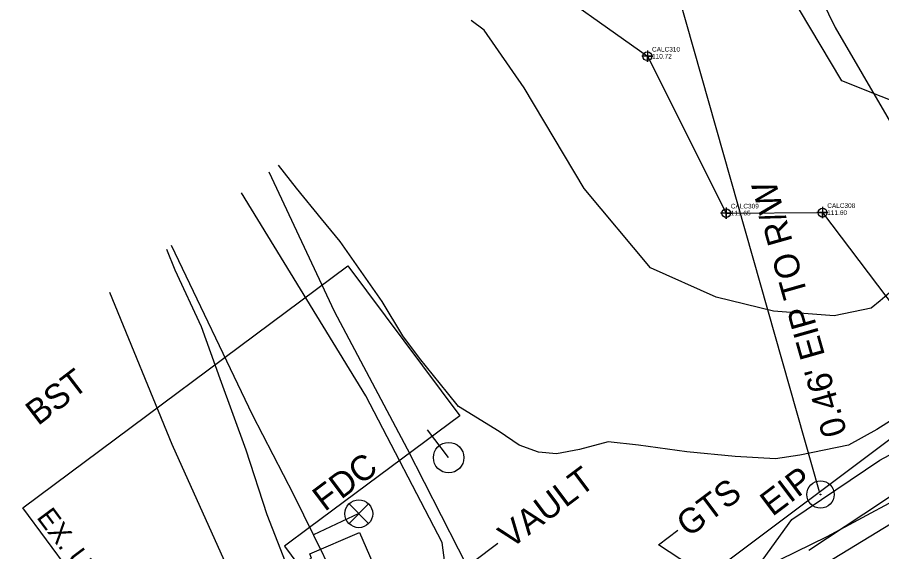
# Model space of a CAD drawing. Extents: x 2186615 to 2188822, y 629899 to 631820.
# Drawn here: x 2187114.7 to 2187253.2, y 630486.1 to 630571.8 of the extents above; entities that cross this region are included whole.
import ezdxf

# ---------------------------------------------------------------- set-up
doc = ezdxf.new("R2010")
doc.units = 0
for name, color, linetype in [('Exist Environmental Wetland Boundary', 7, 'Continuous'), ('Exist Environmental Wetland Boundary Cogo Elevation', 7, 'Continuous'), ('Exist Environmental Wetland Boundary Cogo Number', 7, 'Continuous'), ('Exist Environmental Wetland Boundary Cogo Point CELL', 7, 'Continuous'), ('Exist Guardrail', 7, 'Continuous'), ('Exist Hydro Stream or Body of Water', 7, 'Continuous'), ('Exist Other Culture Area Outline', 7, 'Continuous'), ('Exist Other Culture Area Outline Leader', 7, 'Continuous'), ('Exist Other Culture Area Outline Text', 7, 'Continuous'), ('Exist Other Culture Located Object Leader', 7, 'Continuous'), ('Exist Other Culture Located Object Text', 7, 'Continuous'), ('Exist Property Iron Pin CELL', 7, 'Continuous'), ('Exist Property Iron Pin Text', 7, 'Continuous'), ('Exist Property Line', 7, 'Continuous'), ('Exist Property Line Text', 7, 'Continuous'), ('Exist Right of Way Easement Line', 7, 'Continuous'), ('Exist Right of Way Easement Line Text', 7, 'Continuous'), ('Exist Right of Way Line', 7, 'Continuous'), ('Exist Roads EOP Other', 7, 'Continuous'), ('Exist Roads EOP Text', 7, 'Continuous'), ('Exist Utilities Gas UG Line SUE LOS B', 7, 'Continuous'), ('Exist Utilities Power Pole CELL', 7, 'Continuous'), ('Exist Utilities Telephone UG FO SUE LOS B', 7, 'Continuous'), ('Exist Utilities TV UG Cable SUE LOS B', 7, 'Continuous'), ('Exist Utilities TV UG FO Cable SUE LOS B', 7, 'Continuous'), ('Exist Utilities Water UG Line SUE LOS B', 7, 'Continuous'), ('Exist Utilities Water Valve CELL', 7, 'Continuous'), ('Exist Utilities Water Valve Text', 7, 'Continuous'), ('Exist Vegetation Hedge Row', 7, 'Continuous'), ('Exist Vegetation Woods Line', 7, 'Continuous')]:
    doc.layers.add(name, color=color, linetype=linetype)

msp = doc.modelspace()

# ---------------------------------------------------------------- linework, layer by layer
at = {"layer": 'Exist Environmental Wetland Boundary'}
msp.add_lwpolyline([(2187196.86, 630579.01), (2187215.67, 630565.57), (2187228.3, 630540.41), (2187243.76, 630540.49), (2187258.39, 630521.14), (2187263.98, 630539.96), (2187274.49, 630549.88), (2187286.39, 630545.46), (2187287.92, 630561.15), (2187317.91, 630575.27)], dxfattribs=at)
at = {"layer": 'Exist Environmental Wetland Boundary Cogo Point CELL'}
for points in [[(2187215.67, 630566.47), (2187215.67, 630564.67), (2187215.67, 630565.57), (2187216.57, 630565.57), (2187214.77, 630565.57)], [(2187228.3, 630541.31), (2187228.3, 630539.51), (2187228.3, 630540.41), (2187229.2, 630540.41), (2187227.4, 630540.41)], [(2187243.76, 630541.4), (2187243.76, 630539.59), (2187243.76, 630540.49), (2187244.66, 630540.49), (2187242.86, 630540.49)]]:
    msp.add_lwpolyline(points, dxfattribs=at)
for centre in [(2187215.67, 630565.57), (2187228.3, 630540.41), (2187243.76, 630540.49)]:
    msp.add_circle(centre, 0.703, dxfattribs=at)
at = {"layer": 'Exist Guardrail'}
msp.add_lwpolyline([(2187241.55, 630486.35), (2187253.35, 630494.16), (2187264.21, 630501.54), (2187275.16, 630508.92), (2187284.89, 630515.72), (2187294.52, 630522.69), (2187305.63, 630530.63), (2187316.31, 630538.47), (2187330.34, 630548.74), (2187345.5, 630559.82), (2187361.87, 630571.88), (2187380.98, 630586.03), (2187387.1, 630590.71), (2187395.3, 630597.18), (2187406.46, 630605.97), (2187415.25, 630612.83), (2187425.74, 630621.13)], dxfattribs=at)
at = {"layer": 'Exist Hydro Stream or Body of Water'}
msp.add_lwpolyline([(2187355.02, 630682.11), (2187359.11, 630660.66), (2187365.55, 630646.99), (2187357.69, 630636.57), (2187357.4, 630627.18), (2187350.16, 630611.43), (2187334.76, 630604.35), (2187327.14, 630603.04), (2187305.44, 630602.03), (2187285.87, 630601.1), (2187286.96, 630584.08), (2187284.92, 630570.17), (2187265.5, 630554.2), (2187246.84, 630561.62), (2187236.72, 630578.63), (2187228.75, 630591.98), (2187226.12, 630610.41)], dxfattribs=at)
at = {"layer": 'Exist Other Culture Area Outline'}
msp.add_lwpolyline([(2187169.53, 630489.18), (2187173.82, 630479.34), (2187170.02, 630477.66), (2187166.05, 630475.41), (2187165.8, 630475.86), (2187164.11, 630479.85), (2187161.27, 630484.75), (2187161.83, 630485.05), (2187161.55, 630485.74), (2187169.53, 630489.18)], dxfattribs=at)
at = {"layer": 'Exist Other Culture Area Outline Leader'}
msp.add_lwpolyline([(2187168.93, 630482.94), (2187187.8, 630484.54), (2187191.69, 630487.45)], dxfattribs=at)
at = {"layer": 'Exist Other Culture Located Object Leader'}
msp.add_lwpolyline([(2187227.85, 630480.38), (2187217.44, 630487.19), (2187220.58, 630489.55)], dxfattribs=at)
at = {"layer": 'Exist Property Iron Pin CELL'}
for radius in [2.2, 0.0707]:
    msp.add_circle((2187243.42, 630495.29), radius, dxfattribs=at)
at = {"layer": 'Exist Property Line'}
msp.add_line((2187243.29, 630495.73), (2186931.15, 631595.66), dxfattribs=at)
at = {"layer": 'Exist Right of Way Easement Line'}
for p, q in [((2187115.55, 630493.13), (2187167.68, 630531.96)), ((2187167.68, 630531.96), (2187185.6, 630507.9)), ((2187185.6, 630507.9), (2187161.54, 630489.98)), ((2187160.08, 630433.35), (2187115.55, 630493.13)), ((2187161.54, 630489.98), (2187157.53, 630486.99)), ((2187157.53, 630486.99), (2187184.09, 630451.35))]:
    msp.add_line(p, q, dxfattribs=at)
at = {"layer": 'Exist Right of Way Line'}
msp.add_line((2187118.41, 630402.11), (2188502.83, 631440.02), dxfattribs=at)
msp.add_arc((2189028.8, 628141.74), 2893.55, 125.65722, 135.70821, dxfattribs=at)
at = {"layer": 'Exist Roads EOP Other'}
msp.add_lwpolyline([(2187138.6, 630534.63), (2187139.91, 630531.34), (2187144.17, 630522.21), (2187147.14, 630513.9), (2187151.29, 630502.42), (2187154.7, 630492.1), (2187159.33, 630480.16), (2187161, 630476.69)], dxfattribs=at)
at = {"layer": 'Exist Utilities Gas UG Line SUE LOS B'}
msp.add_lwpolyline([(2187126.47, 630392.39), (2187146.75, 630408.06), (2187165.95, 630422.17), (2187183, 630435.52), (2187198.84, 630447.53), (2187220.79, 630463.61), (2187230.74, 630480.09), (2187238.84, 630491.28), (2187252.93, 630500.78), (2187264.62, 630507.02), (2187278.9, 630518.02), (2187291.16, 630525.79), (2187304.76, 630536.93), (2187314.39, 630544.2), (2187331.5, 630558.33), (2187350.48, 630574.64)], dxfattribs=at)
at = {"layer": 'Exist Utilities Power Pole CELL'}
for q in [(2187180.41, 630505.67), (2187183.82, 630501.19)]:
    msp.add_line((2187183.82, 630501.19), q, dxfattribs=at)
msp.add_circle((2187183.82, 630501.19), 2.45, dxfattribs=at)
at = {"layer": 'Exist Utilities Telephone UG FO SUE LOS B'}
for points in [[(2187221.79, 630477.44), (2187244.49, 630488.55), (2187260.77, 630497.3), (2187273.17, 630505), (2187293.43, 630515), (2187319.92, 630532.54), (2187378.48, 630575.93), (2187483.97, 630656.58), (2187503.96, 630671.26), (2187608.06, 630745.86)], [(2187129.46, 630527.76), (2187139.46, 630503.38), (2187147.83, 630484.7), (2187152.04, 630478.59), (2187166.91, 630468.2), (2187180.79, 630460.12), (2187192.4, 630446.46), (2187206, 630427.52), (2187215.4, 630412.66), (2187218.54, 630406.18), (2187228.54, 630393.28)]]:
    msp.add_lwpolyline(points, dxfattribs=at)
at = {"layer": 'Exist Utilities TV UG Cable SUE LOS B'}
msp.add_lwpolyline([(2187116.07, 630419.88), (2187130.29, 630430.32), (2187150.11, 630446.17), (2187165.4, 630458.46), (2187184.72, 630472.95), (2187182.78, 630487.57), (2187170.53, 630511.09), (2187150.61, 630543.66)], dxfattribs=at)
at = {"layer": 'Exist Utilities TV UG FO Cable SUE LOS B'}
msp.add_lwpolyline([(2187116.73, 630410.24), (2187135.27, 630423.28), (2187155.78, 630437.63), (2187172.03, 630450.4), (2187187.01, 630462.63), (2187195.4, 630469.76), (2187188.11, 630481.18), (2187177.24, 630502.53), (2187165.51, 630524.63), (2187155.03, 630546.98)], dxfattribs=at)
at = {"layer": 'Exist Utilities Water UG Line SUE LOS B'}
msp.add_line((2187169.41, 630492.21), (2187162.15, 630488.8), dxfattribs=at)
for points in [[(2187188.37, 630443.02), (2187206.69, 630458.06), (2187226.47, 630472), (2187238.77, 630480.88), (2187255.87, 630491.3), (2187266.08, 630498.06), (2187295.46, 630519.28), (2187306.87, 630527.17), (2187321.34, 630537.5), (2187340.11, 630551.44), (2187356.85, 630563.99), (2187378.55, 630580.27)], [(2187181.75, 630438.12), (2187188.37, 630443.02), (2187184.93, 630448.76), (2187177.6, 630459.46), (2187168.65, 630475.53), (2187158.99, 630495.24), (2187152.4, 630508.06), (2187139.39, 630535.22)]]:
    msp.add_lwpolyline(points, dxfattribs=at)
at = {"layer": 'Exist Utilities Water Valve CELL'}
msp.add_lwpolyline([(2187171, 630493.76), (2187167.85, 630490.61), (2187169.42, 630492.19), (2187171, 630490.61), (2187167.85, 630493.76)], dxfattribs=at)
msp.add_circle((2187169.42, 630492.19), 2.23, dxfattribs=at)
at = {"layer": 'Exist Vegetation Hedge Row'}
msp.add_lwpolyline([(2187260.3, 630510.67), (2187252.46, 630505.7), (2187247.9, 630503.2), (2187240.1, 630501.58), (2187236.19, 630501.01), (2187229.72, 630501.36), (2187221.98, 630502.11), (2187214.26, 630503.2), (2187209.4, 630503.72), (2187204.78, 630502.52), (2187201.09, 630501.79), (2187198.22, 630502.06), (2187195.1, 630503.19), (2187191.94, 630505.4), (2187185.42, 630509.42), (2187183.64, 630511.6), (2187179.15, 630517.13), (2187176.46, 630520.74), (2187173.17, 630526.26), (2187166.42, 630535.84), (2187163.45, 630539.5), (2187159.44, 630544.43), (2187156.56, 630548.13)], dxfattribs=at)
at = {"layer": 'Exist Vegetation Woods Line'}
for points in [[(2187241.53, 630578.9), (2187245.79, 630570.18), (2187258.39, 630548.54), (2187264.48, 630549.54), (2187279.74, 630558.73), (2187298.24, 630567.83), (2187312.22, 630582.21)], [(2187272.05, 630542.7), (2187253.01, 630526.36), (2187251.56, 630525.18), (2187245.61, 630523.94), (2187235.9, 630524.69), (2187226.68, 630526.94), (2187216.2, 630531.64), (2187205.56, 630544.35), (2187195.9, 630560.51), (2187189.52, 630569.74), (2187187.43, 630571.33)]]:
    msp.add_lwpolyline(points, dxfattribs=at)

# ---------------------------------------------------------------- texts
at = {"layer": 'Exist Environmental Wetland Boundary Cogo Elevation'}
for s, p in [('110.72', (2187216.42, 630565.2)), ('111.65', (2187229.05, 630540.04)), ('111.60', (2187244.51, 630540.12))]:
    msp.add_text(s, height=0.75, dxfattribs=at).set_placement(p)
at = {"layer": 'Exist Environmental Wetland Boundary Cogo Number'}
for s, p in [('CALC310', (2187216.42, 630566.32)), ('CALC309', (2187229.05, 630541.16)), ('CALC308', (2187244.51, 630541.24))]:
    msp.add_text(s, height=0.75, dxfattribs=at).set_placement(p)
at = {"layer": 'Exist Other Culture Area Outline Text'}
msp.add_text('VAULT', height=4, rotation=36.8593, dxfattribs=at).set_placement((2187193.73, 630486.48))
at = {"layer": 'Exist Other Culture Located Object Text'}
msp.add_text('GTS', height=4, rotation=36.8593, dxfattribs=at).set_placement((2187222.28, 630488.32))
at = {"layer": 'Exist Property Iron Pin Text'}
msp.add_text('EIP', height=4, rotation=37.0582, dxfattribs=at).set_placement((2187235.71, 630491.66))
at = {"layer": 'Exist Property Line Text'}
msp.add_text("0.46' EIP TO R/W", height=4, rotation=105.8429, dxfattribs=at).set_placement((2187247.71, 630505.17))
at = {"layer": 'Exist Right of Way Easement Line Text'}
msp.add_text('EX. UTILITY EASEMENT', height=3.2, rotation=306.6851, dxfattribs=at).set_placement((2187117.68, 630491.61))
at = {"layer": 'Exist Roads EOP Text'}
for s, rotation, p in [('BST', 37.422, (2187118, 630506.22)), ("US 301/NC 96/S BRIGHTLEAF BLVD 32' BST", 37.1238, (2187233.73, 630436.43))]:
    msp.add_text(s, height=4, rotation=rotation, dxfattribs=at).set_placement(p)
at = {"layer": 'Exist Utilities Water Valve Text'}
msp.add_text('FDC', height=4, rotation=36.8593, dxfattribs=at).set_placement((2187163.96, 630492.45))

doc.saveas('drawing.dxf')
